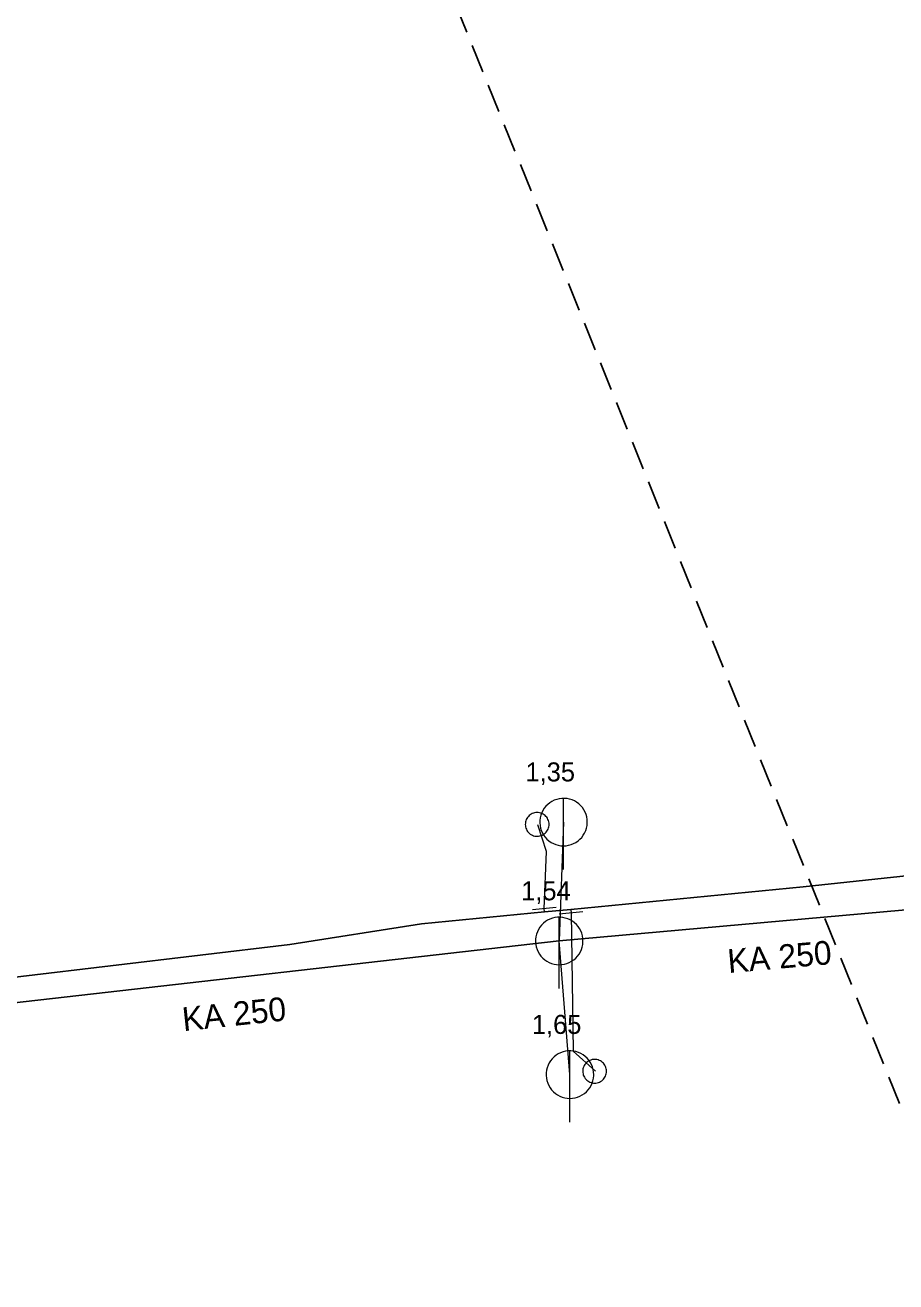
# Model space of a CAD drawing. Extents: x -682839 to -682312, y -994645 to -993949.
# Drawn here: x -682617.8 to -682581.2, y -994271.4 to -994218.6 of the extents above; entities that cross this region are included whole.
import ezdxf

# ---------------------------------------------------------------- set-up
doc = ezdxf.new("R2010")
doc.units = 0
doc.header["$LTSCALE"] = 0.4
doc.linetypes.add('MEDIUM_DASHED', pattern=[4.5, 3, -1.5])
doc.layers.add('1', color=7, linetype='Continuous')
for name, color, linetype, lineweight in [('11', 7, 'Continuous', 13), ('13', 7, 'Continuous', 13), ('14', 7, 'Continuous', 25), ('17', 7, 'Continuous', 25), ('22', 7, 'Continuous', 13), ('23', 7, 'Continuous', 13), ('34', 7, 'Continuous', 13), ('63', 7, 'MEDIUM_DASHED', 25)]:
    doc.layers.add(name, color=color, linetype=linetype, lineweight=lineweight)

msp = doc.modelspace()

# ---------------------------------------------------------------- linework, layer by layer
at = {"layer": '11'}
for p in [(-682595.18, -994252.109), (-682594.91, -994262.73)]:
    msp.add_line(p, (-682595.359, -994257.109), dxfattribs=at)
at = {"layer": '13'}
for points in [[(-682595.989, -994255.75), (-682595.899, -994253.34), (-682596.259, -994252.219)], [(-682594.861, -994255.933), (-682594.78, -994261.739), (-682593.839, -994262.589)]]:
    msp.add_lwpolyline(points, dxfattribs=at)
at = {"layer": '14'}
for p, q in [((-682575.489, -994255.32), (-682595.359, -994257.109)), ((-682595.359, -994257.109), (-682621.469, -994260.079))]:
    msp.add_line(p, q, dxfattribs=at)
at = {"layer": '14', "lineweight": 13}
for p, q in [((-682595.977, -994255.888), (-682595.989, -994255.75)), ((-682594.877, -994255.783), (-682594.861, -994255.933))]:
    msp.add_line(p, q, dxfattribs=at)
at = {"layer": '17'}
msp.add_lwpolyline([(-682575, -994253.756), (-682585.09, -994254.838), (-682594.877, -994255.783), (-682595.977, -994255.888), (-682601.16, -994256.39), (-682606.69, -994257.25), (-682621.798, -994259.055), (-682622.134, -994259.092), (-682631.52, -994260.16), (-682642.26, -994261.399), (-682649.861, -994262.37), (-682651.096, -994262.526), (-682656.289, -994263.19), (-682658.389, -994263.379)], dxfattribs=at)
at = {"layer": '22'}
for p, q in [((-682595.18, -994254.109), (-682595.179, -994251.109)), ((-682595.36, -994259.11), (-682595.359, -994256.11)), ((-682594.91, -994264.73), (-682594.909, -994261.73))]:
    msp.add_line(p, q, dxfattribs=at)
for points in [[(-682594.18, -994252.109), (-682594.185, -994252), (-682594.203, -994251.892), (-682594.233, -994251.786), (-682594.273, -994251.685), (-682594.325, -994251.588), (-682594.387, -994251.498), (-682594.459, -994251.415), (-682594.539, -994251.341), (-682594.627, -994251.275), (-682594.721, -994251.22), (-682594.821, -994251.175), (-682594.926, -994251.142), (-682595.033, -994251.12), (-682595.142, -994251.11), (-682595.252, -994251.112), (-682595.36, -994251.126), (-682595.467, -994251.151), (-682595.57, -994251.188), (-682595.668, -994251.237), (-682595.76, -994251.295), (-682595.846, -994251.364), (-682595.923, -994251.441), (-682595.992, -994251.527), (-682596.051, -994251.619), (-682596.099, -994251.717), (-682596.136, -994251.82), (-682596.162, -994251.927), (-682596.176, -994252.035), (-682596.179, -994252.145), (-682596.169, -994252.254), (-682596.148, -994252.361), (-682596.114, -994252.465), (-682596.07, -994252.565), (-682596.015, -994252.66), (-682595.949, -994252.748), (-682595.875, -994252.828), (-682595.792, -994252.9), (-682595.702, -994252.962), (-682595.606, -994253.014), (-682595.504, -994253.055), (-682595.399, -994253.085), (-682595.291, -994253.103), (-682595.181, -994253.109), (-682595.072, -994253.103), (-682594.964, -994253.085), (-682594.859, -994253.056), (-682594.757, -994253.015), (-682594.66, -994252.963), (-682594.57, -994252.901), (-682594.487, -994252.83), (-682594.412, -994252.75), (-682594.347, -994252.662), (-682594.291, -994252.568), (-682594.247, -994252.468), (-682594.213, -994252.364), (-682594.191, -994252.256), (-682594.181, -994252.147)], [(-682594.36, -994257.11), (-682594.365, -994257.001), (-682594.383, -994256.893), (-682594.413, -994256.787), (-682594.453, -994256.686), (-682594.505, -994256.589), (-682594.567, -994256.499), (-682594.639, -994256.416), (-682594.719, -994256.342), (-682594.807, -994256.276), (-682594.901, -994256.221), (-682595.001, -994256.176), (-682595.106, -994256.143), (-682595.213, -994256.121), (-682595.322, -994256.111), (-682595.432, -994256.113), (-682595.54, -994256.127), (-682595.647, -994256.152), (-682595.75, -994256.189), (-682595.848, -994256.238), (-682595.94, -994256.296), (-682596.026, -994256.365), (-682596.103, -994256.442), (-682596.172, -994256.528), (-682596.231, -994256.62), (-682596.279, -994256.718), (-682596.316, -994256.821), (-682596.342, -994256.928), (-682596.356, -994257.036), (-682596.359, -994257.146), (-682596.349, -994257.255), (-682596.328, -994257.362), (-682596.294, -994257.466), (-682596.25, -994257.566), (-682596.195, -994257.661), (-682596.129, -994257.749), (-682596.055, -994257.829), (-682595.972, -994257.901), (-682595.882, -994257.963), (-682595.786, -994258.015), (-682595.684, -994258.056), (-682595.579, -994258.086), (-682595.471, -994258.104), (-682595.361, -994258.11), (-682595.252, -994258.104), (-682595.144, -994258.086), (-682595.039, -994258.057), (-682594.937, -994258.016), (-682594.84, -994257.964), (-682594.75, -994257.902), (-682594.667, -994257.831), (-682594.592, -994257.751), (-682594.527, -994257.663), (-682594.471, -994257.569), (-682594.427, -994257.469), (-682594.393, -994257.365), (-682594.371, -994257.257), (-682594.361, -994257.148)], [(-682593.91, -994262.73), (-682593.915, -994262.621), (-682593.933, -994262.513), (-682593.963, -994262.407), (-682594.003, -994262.306), (-682594.055, -994262.209), (-682594.117, -994262.119), (-682594.189, -994262.036), (-682594.269, -994261.962), (-682594.357, -994261.896), (-682594.451, -994261.841), (-682594.551, -994261.796), (-682594.656, -994261.763), (-682594.763, -994261.741), (-682594.872, -994261.731), (-682594.982, -994261.733), (-682595.09, -994261.747), (-682595.197, -994261.772), (-682595.3, -994261.809), (-682595.398, -994261.858), (-682595.49, -994261.916), (-682595.576, -994261.985), (-682595.653, -994262.062), (-682595.722, -994262.148), (-682595.781, -994262.24), (-682595.829, -994262.338), (-682595.866, -994262.441), (-682595.892, -994262.548), (-682595.906, -994262.656), (-682595.909, -994262.766), (-682595.899, -994262.875), (-682595.878, -994262.982), (-682595.844, -994263.086), (-682595.8, -994263.186), (-682595.745, -994263.281), (-682595.679, -994263.369), (-682595.605, -994263.449), (-682595.522, -994263.521), (-682595.432, -994263.583), (-682595.336, -994263.635), (-682595.234, -994263.676), (-682595.129, -994263.706), (-682595.021, -994263.724), (-682594.911, -994263.73), (-682594.802, -994263.724), (-682594.694, -994263.706), (-682594.589, -994263.677), (-682594.487, -994263.636), (-682594.39, -994263.584), (-682594.3, -994263.522), (-682594.217, -994263.451), (-682594.142, -994263.371), (-682594.077, -994263.283), (-682594.021, -994263.189), (-682593.977, -994263.089), (-682593.943, -994262.985), (-682593.921, -994262.877), (-682593.911, -994262.768)]]:
    msp.add_lwpolyline(points, close=True, dxfattribs=at)
at = {"layer": '23'}
for points in [[(-682595.886, -994251.905), (-682595.917, -994251.866), (-682595.955, -994251.829), (-682595.998, -994251.796), (-682596.041, -994251.768), (-682596.089, -994251.745), (-682596.137, -994251.726), (-682596.187, -994251.713), (-682596.24, -994251.706), (-682596.291, -994251.704), (-682596.344, -994251.707), (-682596.395, -994251.716), (-682596.446, -994251.729), (-682596.494, -994251.748), (-682596.541, -994251.773), (-682596.585, -994251.801), (-682596.625, -994251.834), (-682596.66, -994251.872), (-682596.693, -994251.913), (-682596.722, -994251.957), (-682596.746, -994252.004), (-682596.764, -994252.053), (-682596.777, -994252.103), (-682596.785, -994252.155), (-682596.788, -994252.207), (-682596.783, -994252.26), (-682596.774, -994252.311), (-682596.761, -994252.361), (-682596.742, -994252.41), (-682596.718, -994252.457), (-682596.689, -994252.501), (-682596.656, -994252.54), (-682596.618, -994252.578), (-682596.578, -994252.61), (-682596.533, -994252.638), (-682596.487, -994252.662), (-682596.439, -994252.68), (-682596.387, -994252.694), (-682596.335, -994252.701), (-682596.283, -994252.703)], [(-682596.129, -994252.678), (-682596.08, -994252.659), (-682596.033, -994252.634), (-682595.991, -994252.605), (-682595.95, -994252.572), (-682595.914, -994252.535), (-682595.881, -994252.493), (-682595.853, -994252.449), (-682595.83, -994252.403), (-682595.811, -994252.354), (-682595.798, -994252.304), (-682595.789, -994252.252), (-682595.788, -994252.198), (-682595.79, -994252.147), (-682595.799, -994252.096), (-682595.812, -994252.046), (-682595.833, -994251.996), (-682595.856, -994251.95), (-682595.886, -994251.905), (-682595.917, -994251.866), (-682595.955, -994251.829), (-682595.998, -994251.796), (-682596.041, -994251.768), (-682596.089, -994251.745), (-682596.137, -994251.726), (-682596.187, -994251.713), (-682596.24, -994251.706), (-682596.291, -994251.704), (-682596.344, -994251.707), (-682596.395, -994251.716), (-682596.446, -994251.729), (-682596.494, -994251.748), (-682596.541, -994251.773), (-682596.585, -994251.801), (-682596.625, -994251.834), (-682596.66, -994251.872), (-682596.693, -994251.913), (-682596.722, -994251.957), (-682596.746, -994252.004), (-682596.764, -994252.053)], [(-682596.764, -994252.053), (-682596.777, -994252.103), (-682596.785, -994252.155), (-682596.788, -994252.207), (-682596.783, -994252.26), (-682596.774, -994252.311), (-682596.761, -994252.361), (-682596.742, -994252.41), (-682596.718, -994252.457), (-682596.689, -994252.501), (-682596.656, -994252.54), (-682596.618, -994252.578), (-682596.578, -994252.61), (-682596.533, -994252.638), (-682596.487, -994252.662), (-682596.439, -994252.68), (-682596.387, -994252.694), (-682596.335, -994252.701), (-682596.283, -994252.703), (-682596.231, -994252.699), (-682596.18, -994252.691), (-682596.129, -994252.678), (-682596.08, -994252.659), (-682596.033, -994252.634), (-682595.991, -994252.605), (-682595.95, -994252.572), (-682595.914, -994252.535), (-682595.881, -994252.493), (-682595.853, -994252.449), (-682595.83, -994252.403), (-682595.811, -994252.354), (-682595.798, -994252.304), (-682595.789, -994252.252), (-682595.788, -994252.198), (-682595.79, -994252.147), (-682595.799, -994252.096), (-682595.812, -994252.046), (-682595.833, -994251.996), (-682595.856, -994251.95), (-682595.886, -994251.905)], [(-682596.283, -994252.703), (-682596.231, -994252.699), (-682596.18, -994252.691), (-682596.129, -994252.678)], [(-682593.496, -994262.921), (-682593.463, -994262.88), (-682593.435, -994262.835), (-682593.413, -994262.789), (-682593.394, -994262.74), (-682593.381, -994262.69), (-682593.374, -994262.637), (-682593.372, -994262.585), (-682593.375, -994262.534), (-682593.383, -994262.482), (-682593.397, -994262.431), (-682593.416, -994262.382), (-682593.441, -994262.335), (-682593.469, -994262.292), (-682593.502, -994262.253), (-682593.539, -994262.216), (-682593.582, -994262.182), (-682593.624, -994262.155), (-682593.673, -994262.131), (-682593.72, -994262.113), (-682593.771, -994262.099), (-682593.824, -994262.093), (-682593.876, -994262.09), (-682593.929, -994262.094), (-682593.98, -994262.101), (-682594.03, -994262.116), (-682594.079, -994262.136), (-682594.125, -994262.159), (-682594.168, -994262.188), (-682594.208, -994262.222), (-682594.246, -994262.259), (-682594.278, -994262.299), (-682594.306, -994262.344), (-682594.33, -994262.391), (-682594.348, -994262.44), (-682594.36, -994262.49), (-682594.368, -994262.542), (-682594.371, -994262.594), (-682594.368, -994262.647), (-682594.359, -994262.699)], [(-682593.673, -994262.131), (-682593.72, -994262.113), (-682593.771, -994262.099), (-682593.824, -994262.093), (-682593.876, -994262.09), (-682593.929, -994262.094), (-682593.98, -994262.101), (-682594.03, -994262.116), (-682594.079, -994262.136), (-682594.125, -994262.159), (-682594.168, -994262.188), (-682594.208, -994262.222), (-682594.246, -994262.259), (-682594.278, -994262.299), (-682594.306, -994262.344), (-682594.33, -994262.391), (-682594.348, -994262.44), (-682594.36, -994262.49), (-682594.368, -994262.542), (-682594.371, -994262.594), (-682594.368, -994262.647), (-682594.359, -994262.699), (-682594.346, -994262.748), (-682594.325, -994262.797), (-682594.303, -994262.844), (-682594.272, -994262.887), (-682594.239, -994262.927), (-682594.202, -994262.964), (-682594.161, -994262.996), (-682594.117, -994263.025), (-682594.07, -994263.049), (-682594.021, -994263.066), (-682593.97, -994263.08), (-682593.919, -994263.088), (-682593.866, -994263.089), (-682593.815, -994263.087), (-682593.763, -994263.078), (-682593.712, -994263.064), (-682593.663, -994263.044), (-682593.617, -994263.02)], [(-682594.359, -994262.699), (-682594.346, -994262.748), (-682594.325, -994262.797), (-682594.303, -994262.844), (-682594.272, -994262.887), (-682594.239, -994262.927), (-682594.202, -994262.964), (-682594.161, -994262.996), (-682594.117, -994263.025), (-682594.07, -994263.049), (-682594.021, -994263.066), (-682593.97, -994263.08), (-682593.919, -994263.088), (-682593.866, -994263.089), (-682593.815, -994263.087), (-682593.763, -994263.078), (-682593.712, -994263.064), (-682593.663, -994263.044), (-682593.617, -994263.02), (-682593.574, -994262.99), (-682593.534, -994262.958), (-682593.496, -994262.921), (-682593.463, -994262.88), (-682593.435, -994262.835), (-682593.413, -994262.789), (-682593.394, -994262.74), (-682593.381, -994262.69), (-682593.374, -994262.637), (-682593.372, -994262.585), (-682593.375, -994262.534), (-682593.383, -994262.482), (-682593.397, -994262.431), (-682593.416, -994262.382), (-682593.441, -994262.335), (-682593.469, -994262.292), (-682593.502, -994262.253), (-682593.539, -994262.216), (-682593.582, -994262.182), (-682593.624, -994262.155), (-682593.673, -994262.131)], [(-682593.617, -994263.02), (-682593.574, -994262.99), (-682593.534, -994262.958), (-682593.496, -994262.921)]]:
    msp.add_lwpolyline(points, dxfattribs=at)
at = {"layer": '34'}
for p, q in [((-682595.491, -994255.702), (-682596.486, -994255.796)), ((-682594.363, -994255.883), (-682595.358, -994255.981))]:
    msp.add_line(p, q, dxfattribs=at)
at = {"layer": '63'}
msp.add_lwpolyline([(-682494.62, -994477.955), (-682564.4, -994570.065), (-682564.4, -994570.065), (-682684.423, -994544.944), (-682684.423, -994544.944), (-682751.412, -994042.525), (-682751.412, -994042.525), (-682670.466, -994042.525), (-682670.466, -994042.525)], close=True, dxfattribs=at)

# ---------------------------------------------------------------- texts
at = {"layer": '1'}
for s, p in [('1,35', (-682596.779, -994250.398)), ('1,54', (-682596.959, -994255.398)), ('1,65', (-682596.51, -994261.018))]:
    msp.add_text(s, height=0.8, dxfattribs=at).set_placement(p)
for rotation, p in [(5, (-682588.234, -994258.461)), (6, (-682611.171, -994260.905))]:
    msp.add_text('KA 250', height=1, rotation=rotation, dxfattribs=at).set_placement(p)

doc.saveas('drawing.dxf')
